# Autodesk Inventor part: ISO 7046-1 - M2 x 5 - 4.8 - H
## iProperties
Created: 2001-08
Part Number: ISO 7046-1 - M2 x 5 - 4.8 - H
Catalog Web Link: file:///D:/Program%20Files/Autodesk/Inventor%205/Content/Iso/index.htm?doNavigateId=D022B3D7-5CFC-471B-AF86-F21EBE825A2A|9823AF26441744E8A8AED6B3477FE8FB|true
Description: Countersunk Flat Head Screw
Document SubType Name: Standard Catalog Part
Standard: ISO 7046-1 - M2 x 5 - 4.8 - H
Designer: Martin Budgell
Control State: 0
Master: False
Checked Out: False
Length Units: 11269
Angle Units: 11279
Time Units: 11290
Mass Units: 11283
Shininess: 3
Angle Display Precision: 2
Document Length Units: 11269
Document Angle Units: 11279
Document Time Units: 11290
Document Mass Units: 11283
Document Length Units Precision: 3
Document Angle Units Precision: 2
Compacted: True
CLASSIFICATION: 31161513 un/spsc
MANUFACTURER: ISO Standard System
Density: 0.0
Volumn: 0.0
Area: 0.0
PropertySet Name: Model Information
Author: Martin Budgell
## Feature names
1. Base1
